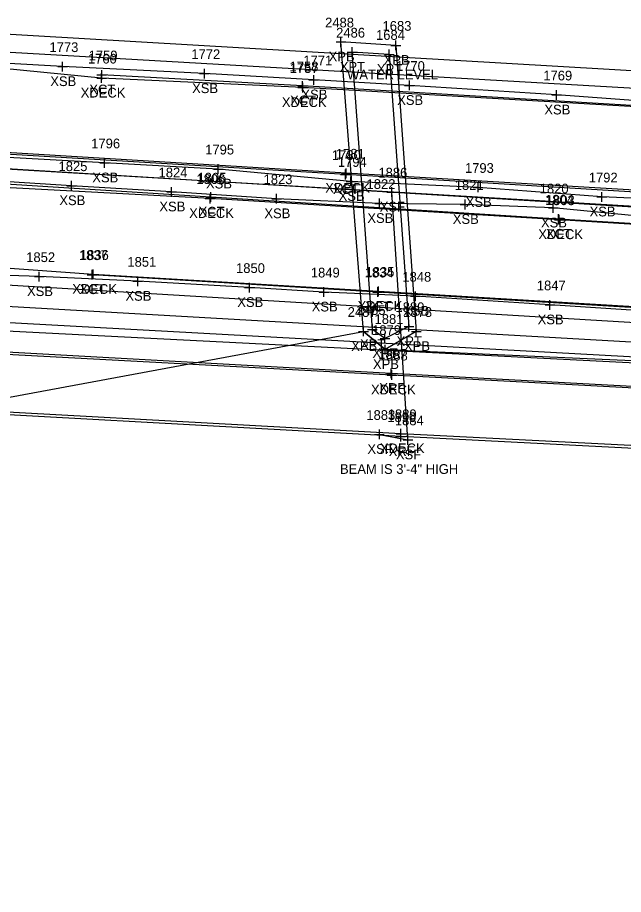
# Model space of a CAD drawing. Extents: x 1461855 to 1464118, y 556196 to 557441.
# Drawn here: x 1462165.9 to 1462228.3, y 556362.8 to 556453 of the extents above; entities that cross this region are included whole.
import ezdxf

# ---------------------------------------------------------------- set-up
doc = ezdxf.new("R2010")
doc.units = 0
for name, color, linetype in [('B_A', 7, 'Continuous'), ('B_C', 7, 'Continuous'), ('B_I', 7, 'Continuous'), ('B_TIC', 7, 'Continuous'), ('BB', 7, 'Continuous'), ('BDC', 7, 'Continuous'), ('BDEFAULT', 7, 'Continuous'), ('BELB', 7, 'Continuous'), ('BR', 7, 'Continuous'), ('BSUBM', 7, 'Continuous'), ('LSOGP', 7, 'Continuous'), ('UW', 7, 'Continuous')]:
    doc.layers.add(name, color=color, linetype=linetype)

msp = doc.modelspace()

# ---------------------------------------------------------------- linework, layer by layer
at = {"layer": 'B_TIC'}
for p, q in [((1462199.239, 556450.484), (1462199.315, 556450.484)), ((1462199.239, 556450.484), (1462199.315, 556450.484)), ((1462204.895, 556450.138), (1462204.97, 556450.138)), ((1462204.895, 556450.138), (1462204.97, 556450.138)), ((1462200.403, 556449.438), (1462200.478, 556449.438)), ((1462200.403, 556449.438), (1462200.478, 556449.438)), ((1462204.224, 556449.203), (1462204.299, 556449.203)), ((1462204.224, 556449.203), (1462204.299, 556449.203)), ((1462170.567, 556447.948), (1462170.642, 556447.948)), ((1462174.603, 556447.094), (1462174.679, 556447.094)), ((1462185.174, 556447.223), (1462185.249, 556447.223)), ((1462174.594, 556446.765), (1462174.669, 556446.765)), ((1462196.432, 556446.584), (1462196.507, 556446.584)), ((1462206.297, 556446.009), (1462206.373, 556446.009)), ((1462195.284, 556445.964), (1462195.359, 556445.964)), ((1462195.315, 556445.79), (1462195.39, 556445.79)), ((1462221.455, 556445.028), (1462221.53, 556445.028)), ((1462174.894, 556438.04), (1462174.97, 556438.04)), ((1462186.604, 556437.408), (1462186.68, 556437.408)), ((1462199.781, 556436.979), (1462199.857, 556436.979)), ((1462199.698, 556436.845), (1462199.773, 556436.845)), ((1462200.267, 556436.133), (1462200.343, 556436.133)), ((1462171.5, 556435.694), (1462171.576, 556435.694)), ((1462213.358, 556435.513), (1462213.434, 556435.513)), ((1462181.802, 556435.051), (1462181.877, 556435.051)), ((1462185.764, 556434.369), (1462185.839, 556434.369)), ((1462185.85, 556434.519), (1462185.926, 556434.519)), ((1462192.618, 556434.352), (1462192.694, 556434.352)), ((1462204.474, 556435.037), (1462204.55, 556435.037)), ((1462226.11, 556434.532), (1462226.186, 556434.532)), ((1462203.223, 556433.862), (1462203.299, 556433.862)), ((1462212.025, 556433.761), (1462212.101, 556433.761)), ((1462221.104, 556433.4), (1462221.179, 556433.4)), ((1462221.65, 556432.248), (1462221.726, 556432.248)), ((1462221.726, 556432.192), (1462221.802, 556432.192)), ((1462168.171, 556426.338), (1462168.246, 556426.338)), ((1462173.6, 556426.538), (1462173.676, 556426.538)), ((1462173.728, 556426.567), (1462173.803, 556426.567)), ((1462178.307, 556425.855), (1462178.383, 556425.855)), ((1462189.824, 556425.214), (1462189.899, 556425.214)), ((1462197.491, 556424.752), (1462197.567, 556424.752)), ((1462203.032, 556424.75), (1462203.108, 556424.75)), ((1462203.116, 556424.823), (1462203.192, 556424.823)), ((1462206.911, 556424.316), (1462206.987, 556424.316)), ((1462220.761, 556423.428), (1462220.837, 556423.428)), ((1462202.488, 556420.896), (1462202.563, 556420.896)), ((1462206.248, 556421.191), (1462206.323, 556421.191)), ((1462201.561, 556420.694), (1462201.637, 556420.694)), ((1462203.765, 556419.97), (1462203.841, 556419.97)), ((1462206.995, 556420.691), (1462207.071, 556420.691)), ((1462203.801, 556418.832), (1462203.877, 556418.832)), ((1462204.427, 556416.373), (1462204.502, 556416.373)), ((1462204.493, 556416.212), (1462204.568, 556416.212)), ((1462203.204, 556410.094), (1462203.279, 556410.094)), ((1462203.204, 556410.094), (1462203.279, 556410.094)), ((1462205.412, 556410.17), (1462205.487, 556410.17)), ((1462205.405, 556409.871), (1462205.481, 556409.871)), ((1462206.142, 556409.537), (1462206.217, 556409.537))]:
    msp.add_line(p, q, dxfattribs=at)
for points in [[(1462199.236, 556449.984), (1462199.236, 556450.984)], [(1462199.236, 556449.984), (1462199.236, 556450.984)], [(1462204.891, 556449.638), (1462204.891, 556450.638)], [(1462204.891, 556449.638), (1462204.891, 556450.638)], [(1462198.736, 556450.484), (1462199.736, 556450.484)], [(1462198.736, 556450.484), (1462199.736, 556450.484)], [(1462200.4, 556448.938), (1462200.4, 556449.939)], [(1462200.4, 556448.938), (1462200.4, 556449.939)], [(1462204.22, 556448.703), (1462204.22, 556449.703)], [(1462204.22, 556448.703), (1462204.22, 556449.703)], [(1462204.391, 556450.138), (1462205.391, 556450.138)], [(1462204.391, 556450.138), (1462205.391, 556450.138)], [(1462199.9, 556449.438), (1462200.9, 556449.438)], [(1462199.9, 556449.438), (1462200.9, 556449.438)], [(1462203.72, 556449.203), (1462204.72, 556449.203)], [(1462203.72, 556449.203), (1462204.72, 556449.203)], [(1462170.063, 556447.948), (1462171.063, 556447.948)], [(1462170.563, 556447.448), (1462170.563, 556448.448)], [(1462174.1, 556447.094), (1462175.1, 556447.094)], [(1462174.59, 556446.265), (1462174.59, 556447.265)], [(1462174.6, 556446.594), (1462174.6, 556447.594)], [(1462184.67, 556447.223), (1462185.67, 556447.223)], [(1462185.17, 556446.723), (1462185.17, 556447.723)], [(1462196.428, 556446.084), (1462196.428, 556447.084)], [(1462174.09, 556446.765), (1462175.09, 556446.765)], [(1462195.28, 556445.464), (1462195.28, 556446.464)], [(1462195.311, 556445.29), (1462195.311, 556446.29)], [(1462195.928, 556446.584), (1462196.928, 556446.584)], [(1462205.794, 556446.009), (1462206.794, 556446.009)], [(1462206.294, 556445.509), (1462206.294, 556446.509)], [(1462194.78, 556445.964), (1462195.78, 556445.964)], [(1462194.811, 556445.79), (1462195.811, 556445.79)], [(1462221.451, 556444.528), (1462221.451, 556445.528)], [(1462220.951, 556445.028), (1462221.951, 556445.028)], [(1462174.391, 556438.04), (1462175.391, 556438.04)], [(1462174.891, 556437.54), (1462174.891, 556438.54)], [(1462186.601, 556436.908), (1462186.601, 556437.908)], [(1462186.101, 556437.408), (1462187.101, 556437.408)], [(1462199.278, 556436.979), (1462200.278, 556436.979)], [(1462199.694, 556436.345), (1462199.694, 556437.345)], [(1462199.778, 556436.479), (1462199.778, 556437.479)], [(1462171.497, 556435.194), (1462171.497, 556436.194)], [(1462199.194, 556436.845), (1462200.194, 556436.845)], [(1462199.764, 556436.133), (1462200.764, 556436.133)], [(1462200.264, 556435.633), (1462200.264, 556436.633)], [(1462170.997, 556435.694), (1462171.997, 556435.694)], [(1462181.798, 556434.551), (1462181.798, 556435.551)], [(1462204.471, 556434.537), (1462204.471, 556435.537)], [(1462212.855, 556435.513), (1462213.855, 556435.513)], [(1462213.355, 556435.013), (1462213.355, 556436.013)], [(1462181.298, 556435.051), (1462182.298, 556435.051)], [(1462185.26, 556434.369), (1462186.26, 556434.369)], [(1462185.347, 556434.519), (1462186.347, 556434.519)], [(1462185.76, 556433.869), (1462185.76, 556434.869)], [(1462185.847, 556434.019), (1462185.847, 556435.019)], [(1462192.115, 556434.352), (1462193.115, 556434.352)], [(1462192.615, 556433.852), (1462192.615, 556434.852)], [(1462203.22, 556433.362), (1462203.22, 556434.362)], [(1462203.971, 556435.037), (1462204.971, 556435.037)], [(1462212.022, 556433.261), (1462212.022, 556434.261)], [(1462225.607, 556434.532), (1462226.607, 556434.532)], [(1462226.107, 556434.032), (1462226.107, 556435.032)], [(1462202.72, 556433.862), (1462203.72, 556433.862)], [(1462211.522, 556433.761), (1462212.522, 556433.761)], [(1462220.6, 556433.4), (1462221.6, 556433.4)], [(1462221.1, 556432.9), (1462221.1, 556433.9)], [(1462221.647, 556431.748), (1462221.647, 556432.748)], [(1462221.723, 556431.692), (1462221.723, 556432.692)], [(1462221.147, 556432.248), (1462222.147, 556432.248)], [(1462221.223, 556432.192), (1462222.223, 556432.192)], [(1462173.597, 556426.038), (1462173.597, 556427.038)], [(1462173.724, 556426.067), (1462173.724, 556427.067)], [(1462167.667, 556426.338), (1462168.667, 556426.338)], [(1462168.167, 556425.838), (1462168.167, 556426.838)], [(1462173.097, 556426.538), (1462174.097, 556426.538)], [(1462173.224, 556426.567), (1462174.224, 556426.567)], [(1462178.304, 556425.355), (1462178.304, 556426.355)], [(1462177.804, 556425.855), (1462178.804, 556425.855)], [(1462189.82, 556424.714), (1462189.82, 556425.714)], [(1462197.488, 556424.252), (1462197.488, 556425.252)], [(1462203.029, 556424.25), (1462203.029, 556425.25)], [(1462203.113, 556424.323), (1462203.113, 556425.323)], [(1462189.32, 556425.214), (1462190.32, 556425.214)], [(1462196.988, 556424.752), (1462197.988, 556424.752)], [(1462202.529, 556424.75), (1462203.529, 556424.75)], [(1462202.613, 556424.823), (1462203.613, 556424.823)], [(1462206.908, 556423.816), (1462206.908, 556424.816)], [(1462206.408, 556424.316), (1462207.408, 556424.316)], [(1462220.258, 556423.428), (1462221.258, 556423.428)], [(1462220.758, 556422.928), (1462220.758, 556423.928)], [(1462206.244, 556420.691), (1462206.244, 556421.691)], [(1462201.558, 556420.194), (1462201.558, 556421.194)], [(1462201.984, 556420.896), (1462202.984, 556420.896)], [(1462202.484, 556420.396), (1462202.484, 556421.396)], [(1462205.744, 556421.191), (1462206.744, 556421.191)], [(1462206.992, 556420.191), (1462206.992, 556421.191)], [(1462201.058, 556420.694), (1462202.058, 556420.694)], [(1462203.262, 556419.97), (1462204.262, 556419.97)], [(1462203.762, 556419.47), (1462203.762, 556420.471)], [(1462206.492, 556420.691), (1462207.492, 556420.691)], [(1462203.798, 556418.332), (1462203.798, 556419.332)], [(1462203.298, 556418.832), (1462204.298, 556418.832)], [(1462203.923, 556416.373), (1462204.923, 556416.373)], [(1462203.989, 556416.212), (1462204.989, 556416.212)], [(1462204.423, 556415.873), (1462204.423, 556416.873)], [(1462204.489, 556415.712), (1462204.489, 556416.712)], [(1462202.7, 556410.094), (1462203.7, 556410.094)], [(1462202.7, 556410.094), (1462203.7, 556410.094)], [(1462203.2, 556409.594), (1462203.2, 556410.594)], [(1462203.2, 556409.594), (1462203.2, 556410.594)], [(1462204.908, 556410.17), (1462205.908, 556410.17)], [(1462205.402, 556409.371), (1462205.402, 556410.371)], [(1462205.408, 556409.67), (1462205.408, 556410.67)], [(1462206.138, 556409.037), (1462206.138, 556410.037)], [(1462204.902, 556409.871), (1462205.902, 556409.871)], [(1462205.638, 556409.537), (1462206.638, 556409.537)]]:
    msp.add_lwpolyline(points, dxfattribs=at)
at = {"layer": 'BB'}
for points in [[(1462330.314, 556439.882), (1462152.032, 556450.172)], [(1462330.281, 556438.56), (1462322.158, 556439.115), (1462315.056, 556439.347), (1462311.157, 556439.545), (1462298.612, 556440.288), (1462285.489, 556441.028), (1462275.964, 556441.553), (1462262.291, 556442.26), (1462250.561, 556442.934), (1462239.101, 556443.725), (1462221.451, 556445.028), (1462206.294, 556446.009), (1462196.428, 556446.584), (1462185.17, 556447.223), (1462170.563, 556447.948), (1462158.846, 556448.597), (1462153.063, 556449.174)], [(1462328.781, 556428.634), (1462324.065, 556428.892), (1462319.456, 556429.171), (1462319.262, 556429.313), (1462304.716, 556430.256), (1462292.982, 556430.953), (1462284.287, 556431.363), (1462273.947, 556431.84), (1462261.623, 556432.561), (1462248.124, 556433.552), (1462226.107, 556434.532), (1462213.355, 556435.513), (1462200.264, 556436.133), (1462186.601, 556437.408), (1462174.891, 556438.04), (1462163.053, 556438.684), (1462157.864, 556438.972), (1462151.418, 556439.478)], [(1462329.779, 556427.349), (1462151.293, 556438.257)], [(1462328.685, 556426.103), (1462325.057, 556426.385), (1462319.713, 556426.698), (1462318.91, 556426.742), (1462308.703, 556427.372), (1462297.87, 556428.062), (1462287.86, 556428.625), (1462279.228, 556429.453), (1462266.621, 556430.191), (1462257.639, 556430.745), (1462248.392, 556431.143), (1462238.993, 556431.689), (1462230.236, 556432.512), (1462221.1, 556433.4), (1462212.022, 556433.761), (1462203.22, 556433.862), (1462192.615, 556434.352), (1462181.798, 556435.051), (1462171.497, 556435.694), (1462163.387, 556436.205), (1462158.362, 556436.371), (1462151.163, 556436.853)], [(1462329.432, 556416.833), (1462323.508, 556417.23), (1462311.062, 556418.012), (1462310.913, 556418.032), (1462299.309, 556418.758), (1462286.726, 556419.548), (1462277.774, 556420.048), (1462264.748, 556420.883), (1462247.065, 556421.852), (1462234.884, 556422.524), (1462220.758, 556423.428), (1462206.908, 556424.316), (1462197.488, 556424.752), (1462189.82, 556425.214), (1462178.304, 556425.855), (1462168.167, 556426.338), (1462157.727, 556426.705), (1462150.543, 556427.374)], [(1462329.287, 556415.62), (1462150.452, 556426.331)]]:
    msp.add_lwpolyline(points, dxfattribs=at)
at = {"layer": 'BDC'}
for points in [[(1462306.21, 556439.817), (1462267.643, 556441.754), (1462231.479, 556443.795), (1462195.28, 556445.964), (1462174.6, 556447.094)], [(1462330.253, 556427.044), (1462330.307, 556427.885), (1462321.119, 556429.542), (1462284.961, 556431.731), (1462249.264, 556433.812), (1462199.694, 556436.845), (1462158.901, 556439.284), (1462149.578, 556438.742), (1462149.473, 556437.83)], [(1462330.253, 556427.044), (1462320.906, 556426.297), (1462302.96, 556427.514), (1462266.959, 556429.497), (1462221.647, 556432.248), (1462185.847, 556434.519), (1462158.743, 556436.243), (1462149.473, 556437.83)], [(1462304.967, 556418.828), (1462275.389, 556420.423), (1462239.223, 556422.53), (1462203.029, 556424.75), (1462173.597, 556426.538)]]:
    msp.add_lwpolyline(points, dxfattribs=at)
at = {"layer": 'BDEFAULT'}
for points in [[(1462340.791, 556440.982), (1462140.486, 556452.697)], [(1462339.926, 556427), (1462139.852, 556438.871)], [(1462203.2, 556410.094), (1462206.138, 556409.537), (1462204.471, 556435.037)], [(1462339.234, 556413.311), (1462138.867, 556424.749)], [(1462328.804, 556412.4), (1462155.31, 556421.202)]]:
    msp.add_lwpolyline(points, dxfattribs=at)
at = {"layer": 'BELB'}
for points in [[(1462332.261, 556438.564), (1462306.157, 556439.369), (1462267.585, 556441.59), (1462231.402, 556443.714), (1462195.311, 556445.79), (1462174.59, 556446.765), (1462149.769, 556449.202)], [(1462330.387, 556427.996), (1462321.219, 556429.671), (1462285.084, 556431.77), (1462249.268, 556434.079), (1462199.778, 556436.979), (1462159.012, 556439.444), (1462149.101, 556439.166)], [(1462330.387, 556427.996), (1462330.292, 556426.802), (1462320.892, 556426.149), (1462302.888, 556427.151), (1462266.996, 556429.395), (1462221.723, 556432.192), (1462185.76, 556434.369), (1462158.715, 556435.82), (1462149.068, 556437.555)], [(1462331.212, 556416.788), (1462304.91, 556418.948), (1462275.378, 556420.599), (1462239.194, 556422.631), (1462203.113, 556424.823), (1462173.724, 556426.567), (1462149.901, 556428.267), (1462148.306, 556426.947)], [(1462337.183, 556408.895), (1462260.894, 556413.183), (1462204.489, 556416.212), (1462146.838, 556419.281)], [(1462336.881, 556403.082), (1462260.891, 556407.332), (1462205.408, 556410.17), (1462146.764, 556413.378)]]:
    msp.add_lwpolyline(points, dxfattribs=at)
at = {"layer": 'BR'}
for points in [[(1462338.998, 556414.351), (1462338.8, 556409.121), (1462204.423, 556416.373), (1462146.886, 556419.56), (1462146.979, 556424.973)], [(1462356.157, 556401.791), (1462336.856, 556402.851), (1462260.866, 556407.054), (1462205.402, 556409.871), (1462146.909, 556413.108), (1462126.732, 556414.71), (1462111.281, 556416.663), (1462102.284, 556418.456)]]:
    msp.add_lwpolyline(points, dxfattribs=at)
at = {"layer": 'BSUBM'}
for points in [[(1462204.891, 556450.138), (1462206.992, 556420.691), (1462203.798, 556418.832), (1462201.558, 556420.694), (1462199.236, 556450.484)], [(1462204.891, 556450.138), (1462199.236, 556450.484)], [(1462204.22, 556449.203), (1462206.244, 556421.191), (1462203.762, 556419.97), (1462202.484, 556420.896), (1462200.4, 556449.438)], [(1462204.22, 556449.203), (1462200.4, 556449.438)]]:
    msp.add_lwpolyline(points, dxfattribs=at)
at = {"layer": 'LSOGP'}
msp.add_lwpolyline([(1462152.286, 556411.553), (1462201.558, 556420.694), (1462202.678, 556419.763), (1462203.798, 556418.832), (1462262.402, 556416.239), (1462263.085, 556416.638), (1462263.768, 556417.037), (1462264.45, 556417.436), (1462265.133, 556417.835), (1462322.28, 556416.088), (1462328.247, 556406.014), (1462332.388, 556400.161), (1462335.319, 556389.349), (1462336.388, 556385.542), (1462337.181, 556366.3), (1462343.781, 556341.464)], dxfattribs=at)
at = {"layer": 'UW'}
msp.add_lwpolyline([(1462337.589, 556410.109), (1462335.376, 556410.001), (1462332.293, 556412.43), (1462148.132, 556422.524)], dxfattribs=at)

# ---------------------------------------------------------------- texts
at = {"layer": 'B_A'}
for s, p in [('XPB', (1462197.972, 556448.484)), ('XPB', (1462197.972, 556448.484)), ('XPB', (1462203.627, 556448.138)), ('XPB', (1462203.627, 556448.138)), ('XPT', (1462199.12, 556447.438)), ('XPT', (1462199.12, 556447.438)), ('XPT', (1462202.941, 556447.203)), ('XPT', (1462202.941, 556447.203)), ('XSB', (1462169.3, 556445.948)), ('XCT', (1462173.32, 556445.094)), ('XSB', (1462183.907, 556445.223)), ('XDECK', (1462172.433, 556444.765)), ('XSB', (1462195.164, 556444.584)), ('XDECK', (1462193.154, 556443.79)), ('XCT', (1462194.001, 556443.964)), ('XSB', (1462205.03, 556444.009)), ('XSB', (1462220.187, 556443.028)), ('XSB', (1462173.627, 556436.04)), ('XSB', (1462185.337, 556435.408)), ('XDECK', (1462197.62, 556434.979)), ('XCT', (1462198.415, 556434.845)), ('XSB', (1462170.233, 556433.694)), ('XSB', (1462199, 556434.133)), ('XSB', (1462212.091, 556433.513)), ('XSB', (1462180.535, 556433.051)), ('XDECK', (1462183.603, 556432.369)), ('XCT', (1462184.567, 556432.519)), ('XSB', (1462191.351, 556432.352)), ('XSF', (1462203.231, 556433.037)), ('XSB', (1462224.843, 556432.532)), ('XSB', (1462201.956, 556431.862)), ('XSB', (1462210.758, 556431.761)), ('XSB', (1462219.836, 556431.4)), ('XDECK', (1462219.565, 556430.192)), ('XCT', (1462220.367, 556430.248)), ('XSB', (1462166.903, 556424.338)), ('XDECK', (1462171.567, 556424.567)), ('XCT', (1462172.317, 556424.538)), ('XSB', (1462177.04, 556423.855)), ('XSB', (1462188.557, 556423.214)), ('XSB', (1462196.224, 556422.752)), ('XDECK', (1462200.955, 556422.823)), ('XCT', (1462201.749, 556422.75)), ('XSB', (1462205.644, 556422.316)), ('XSB', (1462219.494, 556421.428)), ('XPT', (1462201.205, 556418.896)), ('XPT', (1462204.965, 556419.191)), ('XPB', (1462200.294, 556418.694)), ('XPT', (1462202.482, 556417.97)), ('XPB', (1462205.728, 556418.691)), ('XPB', (1462202.534, 556416.832)), ('XRF', (1462203.183, 556414.373)), ('XDECK', (1462202.332, 556414.212)), ('XSF', (1462201.96, 556408.094)), ('XSF', (1462201.96, 556408.094)), ('XDECK', (1462203.251, 556408.17)), ('XRF', (1462204.162, 556407.871)), ('XSF', (1462204.898, 556407.537))]:
    msp.add_text(s, height=1, dxfattribs=at).set_placement(p)
at = {"layer": 'B_C'}
for s, p in [('WATER LEVEL', (1462199.867, 556446.638)), ('WATER LEVEL', (1462199.867, 556446.638)), ('BEAM IS 3\'-4" HIGH', (1462199.138, 556406.037))]:
    msp.add_text(s, height=1, dxfattribs=at).set_placement(p)
at = {"layer": 'B_I'}
for s, p in [('2488', (1462197.606, 556451.984)), ('2488', (1462197.606, 556451.984)), ('1683', (1462203.521, 556451.638)), ('1683', (1462203.521, 556451.638)), ('2486', (1462198.742, 556450.938)), ('2486', (1462198.742, 556450.938)), ('1684', (1462202.85, 556450.703)), ('1684', (1462202.85, 556450.703)), ('1773', (1462169.217, 556449.448)), ('1759', (1462173.249, 556448.594)), ('1772', (1462183.824, 556448.723)), ('1760', (1462173.177, 556448.265)), ('1771', (1462195.365, 556448.084)), ('1758', (1462193.934, 556447.464)), ('1757', (1462193.965, 556447.29)), ('1770', (1462204.904, 556447.509)), ('1769', (1462220.077, 556446.528)), ('1796', (1462173.517, 556439.54)), ('1795', (1462185.254, 556438.908)), ('1780', (1462198.304, 556438.345)), ('1781', (1462198.715, 556438.479)), ('1825', (1462170.15, 556437.194)), ('1794', (1462198.918, 556437.633)), ('1793', (1462212.008, 556437.013)), ('1824', (1462180.452, 556436.551)), ('1805', (1462184.461, 556436.019)), ('1886', (1462203.097, 556436.537)), ('1792', (1462224.76, 556436.032)), ('1806', (1462184.347, 556435.869)), ('1823', (1462191.268, 556435.852)), ('1822', (1462201.874, 556435.362)), ('1821', (1462210.959, 556435.261)), ('1820', (1462219.71, 556434.9)), ('1804', (1462220.261, 556433.748)), ('1803', (1462220.337, 556433.692)), ('1852', (1462166.821, 556427.838)), ('1837', (1462172.25, 556428.038)), ('1836', (1462172.35, 556428.067)), ('1851', (1462177.241, 556427.355)), ('1850', (1462188.431, 556426.714)), ('1849', (1462196.137, 556426.252)), ('1834', (1462201.682, 556426.25)), ('1835', (1462201.766, 556426.323)), ('1848', (1462205.561, 556425.816)), ('1847', (1462219.411, 556424.928)), ('1880', (1462204.854, 556422.691)), ('2487', (1462199.928, 556422.194)), ('2485', (1462200.854, 556422.396)), ('1878', (1462205.645, 556422.191)), ('1881', (1462202.699, 556421.47)), ('1879', (1462202.447, 556420.332)), ('1887', (1462203.077, 556417.873)), ('1888', (1462203.143, 556417.712)), ('1883', (1462201.854, 556411.594)), ('1883', (1462201.854, 556411.594)), ('1889', (1462204.058, 556411.67)), ('1890', (1462204.012, 556411.371)), ('1884', (1462204.792, 556411.037))]:
    msp.add_text(s, height=1, dxfattribs=at).set_placement(p)

doc.saveas('drawing.dxf')
